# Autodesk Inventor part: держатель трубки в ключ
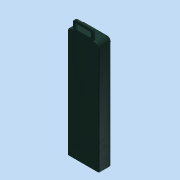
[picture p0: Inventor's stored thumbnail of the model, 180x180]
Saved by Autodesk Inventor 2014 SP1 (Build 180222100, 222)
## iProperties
Created: 2015-10
Part Number: держатель трубки в ключ
Material: Пластик ПБТ
Document SubType Name: Modeling
Designer: hals
Density: 1.31 g/cm^3
Appearance: Гладкий - белый
Author: hals
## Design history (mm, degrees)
sketch "Эскиз1"
  geometry: L1 (17, -60)-(-17, -60); L2 (-17, -60)-(-17, 55); L3 (17, 55)-(17, -60); L4 (17, -60)-(-17, 60); L5 (-17, -60)-(17, 60); L6 (11, 60)-(11, 66.5); L7 (7.5, 70)-(-7.5, 70); L8 (-11, 66.5)-(-11, 60); L9 (-11, 50)-(11, 70); L10 (11, 50)-(-11, 70); L11 (-6.754, 67)-(6.754, 67); L12 (8.754, 65)-(8.754, 63.446); L13 (6.754, 61.446)-(-6.754, 61.446); L14 (-8.754, 63.446)-(-8.754, 65); L15 (-12, 60)-(-11, 60); L16 (11, 60)-(12, 60); L17 (-11, 60)-(11, 60); A1 r 3.5 centre (-7.5, 66.5) between (-7.5, 70) and (-11, 66.5); A2 r 3.5 centre (7.5, 66.5) between (11, 66.5) and (7.5, 70); A3 r 2 centre (-6.754, 65) between (-6.754, 67) and (-8.754, 65); A4 r 2 centre (-6.754, 63.446) between (-8.754, 63.446) and (-6.754, 61.446); A5 r 2 centre (6.754, 63.446) between (6.754, 61.446) and (8.754, 63.446); A6 r 2 centre (6.754, 65) between (8.754, 65) and (6.754, 67); A7 r 5 centre (-12, 55) between (-12, 60) and (-17, 55); A8 r 5 centre (12, 55) between (17, 55) and (12, 60); 2 further points
  constraints: 34 end point, 16 point on circle, 16 tangent, 8 centre point, 8 point on line, 6 parallel, 5 equal radius, 4 midpoint, 2 horizontal, 2 perpendicular, 1 collinear
  dimensions: "d0" = 34 distance of L4.end L5.end; "d1" = 120 distance of L1.end L4.end; "d2" = 10 distance from line of L7 point (0, 60); "d3" = 22 distance of L9.end L10.end; "d4" = 3 distance between parallel lines of L7 L11; "d5" = 2.246 distance between parallel lines of L8 L14; "d6" = 2.24571 distance between parallel lines of L6 L12; "d7" = 3.5 radius of A1; "d8" = 2 radius of A3; "d9" = 5 radius of A7
extrude "Выдавливание1" new body sketch "Эскиз1" distance "d10" = 2; taper "d11" = 0 deg
sketch "Эскиз2"
  geometry: L1 (11, -60)-(12, -60) reference; L2 (17, -55)-(17, 60) reference; L3 (17, 60)-(-17, 60) reference; L4 (-17, 60)-(-17, -55) reference; L5 (-12, -60)-(-11, -60) reference; L6 (-11, -60)-(11, -60); A1 r 5 centre (12, -55) between (12, -60) and (17, -55) reference; A2 r 5 centre (-12, -55) between (-17, -55) and (-12, -60) reference; 1 further point
  constraints: 2 end point, 1 collinear
extrude "Выдавливание2" join sketch "Эскиз2" distance "d12" = 13; taper "d13" = 0 deg
fillet "Сопряжение1" dims "d14" = 4
fillet "Сопряжение4" dims "d17" = 1
sketch "Эскиз3"
  geometry: L1 (13, 60)-(-13, 60) reference; L2 (-11, 54)-(11, 54); L3 (11, 54)-(11, 57.5); L4 (-11, 57.5)-(-11, 54); L5 (-11, 54)-(11, 57.5); L6 (11, 54)-(-11, 57.5); L7 (0, 60)-(0, 58.099); L8 (0, 55.75)-(0, 56.209); L9 (-8.735, 57.5)-(-8.735, 60); L10 (-8.735, 60)-(8.735, 60); L11 (8.735, 60)-(8.735, 57.5); L12 (8.735, 55)-(-8.735, 60); L13 (-8.735, 55)-(8.735, 60); L14 (11, 57.5)-(8.735, 57.5); L15 (-8.735, 57.5)-(-11, 57.5); 2 further points
  constraints: 28 end point, 5 midpoint, 5 parallel, 2 collinear, 1 horizontal, 1 perpendicular, 1 point on line
  dimensions: "d19" = 22 distance of L2.start L2.end; "d20" = 3.5 distance of L4.start L2.start
extrude "Выдавливание3" cut sketch "Эскиз3" distance "d21" = 13; taper "d22" = 0 deg
node "Твердое тело1"
other parameters: "d18" = 2.5
